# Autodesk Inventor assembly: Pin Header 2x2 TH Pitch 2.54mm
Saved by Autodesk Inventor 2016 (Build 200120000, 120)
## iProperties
Created: 2018-05
Part Number: Pin Header 2x2 TH Pitch 2.54mm
Document SubType Name: Assembly
Designer: Administrator
Title: Pin Header 2x2 TH Pitch 2.54mm v1
Author: Administrator
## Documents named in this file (3)
- c:\worker\convert-fusion-mar-2018\tmp\job-1\16\output\files\8c58ff39-88bb-4352-afd9-60265520bae5\Pin Header 2x2 TH Pitch 2.54mm v1.iam
- c:\worker\convert-fusion-mar-2018\tmp\job-1\16\output\files\8c58ff39-88bb-4352-afd9-60265520bae5\pins_1.ipt
- c:\worker\convert-fusion-mar-2018\tmp\job-1\16\output\files\8c58ff39-88bb-4352-afd9-60265520bae5\spacers_1.iam
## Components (2 placed, 2 different names)
1. pins:1
2. spacers:1 [sub-assembly]
